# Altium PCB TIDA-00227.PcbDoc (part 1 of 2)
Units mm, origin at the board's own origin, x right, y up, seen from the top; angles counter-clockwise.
Board outline 100 x 100 mm, 2 copper layers (Top Layer, Bottom Layer), stack 1.575 mm thick; 148 components, 67 nets, 312 pads, 76 vias.
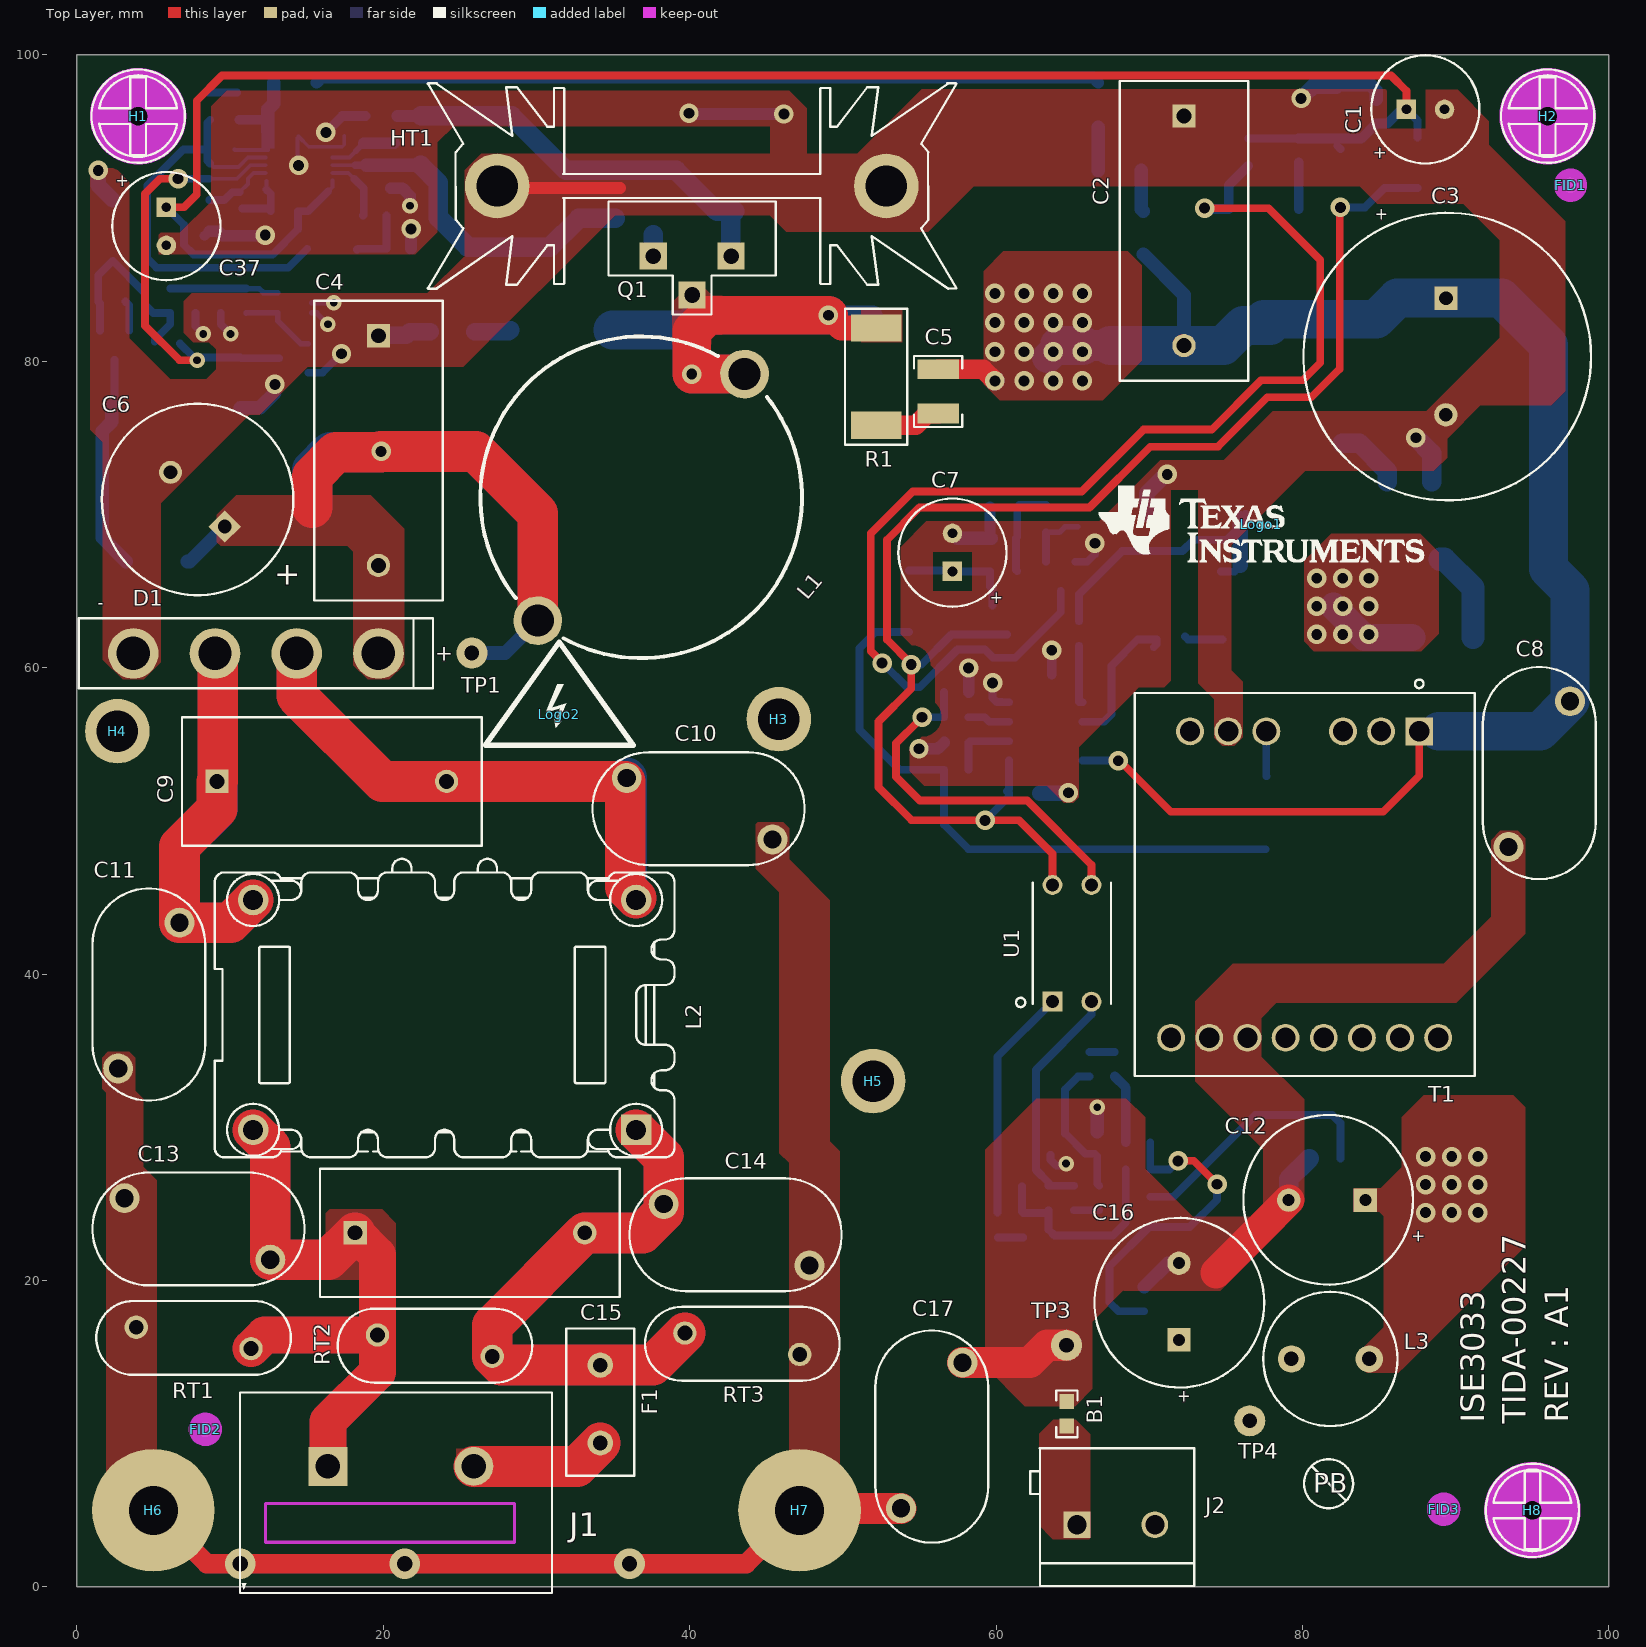
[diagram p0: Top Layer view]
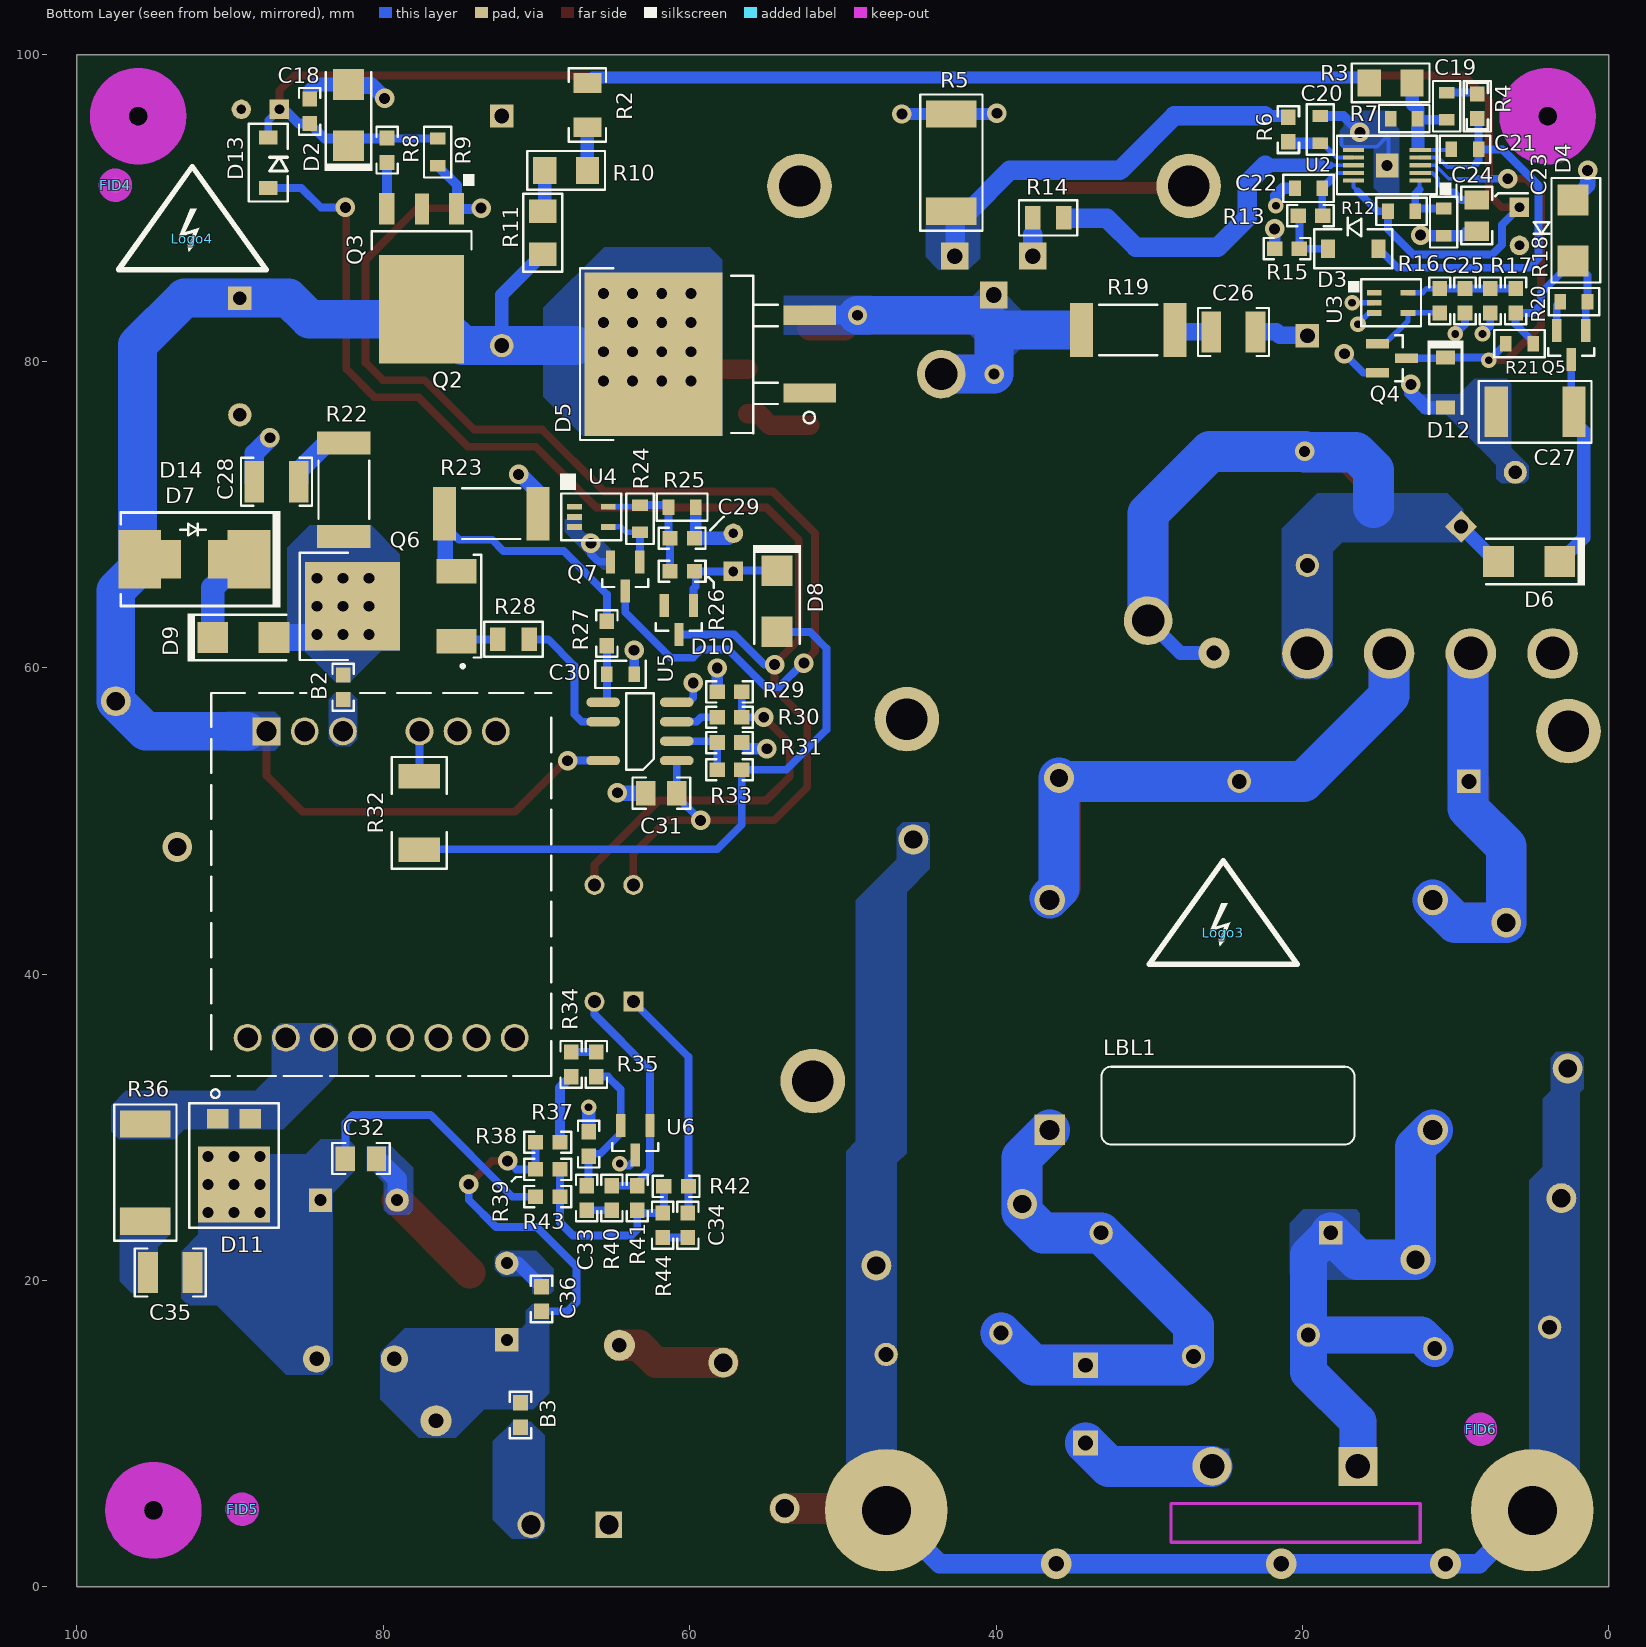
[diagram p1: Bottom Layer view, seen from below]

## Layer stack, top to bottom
Top Layer: signal copper 0.0356
Dielectric: core 1.5037, FR-4, Dk 4.8
Bottom Layer: signal copper 0.0356

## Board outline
0,0 100,0 100,100 0,100

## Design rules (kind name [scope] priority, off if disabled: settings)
AcuteAngle [All] p1: minimum=4.50000000000000E+0001 checktracksonly=FALSE
AssemblyTestPointUsage [All] p1: valid=2
Clearance Clearance_TH [IsVia vs IsThruPin] p1: gap=0.381
Clearance "Clearance_SMT to Via" [IsSMTPin vs IsVia] p2: gap=0.381
Clearance "Clearance_Via to Via" [IsVia vs IsVia] p3: gap=0.305
Clearance "Clearance_Poly to Poly" [InPolygon vs InPolygon] p4: gap=0.635
Clearance Clearance_Poly [InPolygon] p5: gap=0.635
Clearance [All] p6: gap=0.203
ComponentClearance ComponentClearance_Logo [InComponentClass('Logo')] p1: gap=1.27 collisioncheckmode=3 verticalgap=0.254 showdistances=FALSE
ComponentClearance ComponentClearance_ScrewToNut [(HasFootprint('NY PMS 440 0025 PH')) vs (HasFootprint('Keystone_1902C'))] p2: gap=0.127 collisioncheckmode=3 verticalgap=0.254 showdistances=FALSE
ComponentClearance ComponentClearance_MountingHoles [InComponentClass('Mounting Holes')] p3: gap=6.35 collisioncheckmode=3 verticalgap=2540 showdistances=FALSE
ComponentClearance ComponentClearance_SmallPassives [HasFootprint('0201*') or HasFootprint('0402*') or HasFootprint('0508') or HasFootprint('0603*') or HasFootprint('0612') or HasFootprint('0805*') or HasFootprint('0815*') or HasFootprint('0830*') or HasFootprint('1206*') or HasFootprint('1210*') or HasFootprint('1808*') or HasFootprint('1812*') or HasFootprint('1825*') or HasFootprint('2010*') or HasFootprint('2220*') or HasFootprint('2225*') or HasFootprint('2512*') or HasFootprint('2728*') or HasFootprint('3518*') vs HasFootprint('0201*') or HasFootprint('0402*') or HasFootprint('0508') or HasFootprint('0603*') or HasFootprint('0612') or HasFootprint('0805*') or HasFootprint('0815*') or HasFootprint('0830*') or HasFootprint('1206*') or HasFootprint('1210*') or HasFootprint('1808*') or HasFootprint('1812*') or HasFootprint('1825*') or HasFootprint('2010*') or HasFootprint('2220*') or HasFootprint('2225*') or HasFootprint('2512*') or HasFootprint('2728*') or HasFootprint('3518*')] p4: gap=0.508 collisioncheckmode=3 verticalgap=0.254 showdistances=FALSE
ComponentClearance ComponentClearance_THtoSMT [IsThruComponent vs IsSMTComponent] p5: gap=2.54 collisioncheckmode=3 verticalgap=0.762 showdistances=FALSE
ComponentClearance ComponentClearance_THtoTH [IsThruComponent vs IsThruComponent] p6: gap=3 collisioncheckmode=3 verticalgap=0.762 showdistances=FALSE
ComponentClearance [All] p7: gap=1.016 collisioncheckmode=3 verticalgap=0.254 showdistances=FALSE
DiffPairsRouting [All] p1: maxlimit=2.54 minlimit=0.254 mostfreqgap=0.254 maxuncoupledlength=25.4
FabricationTestPointUsage TestPointUsage [All] p1: valid=2 allowmultiple=FALSE
FabricationTestpoint Testpoint [All] p1: side=3 testpointundercomponent=TRUE minsize=1.016 maxsize=2.54 preferedsize=1.524 minholesize=0 maxholesize=1.016 preferedholesize=0.813 testpointgrid=0.025 allowsidetop=TRUE allowsidebottom=TRUE usegrid=TRUE gridtolerance=0
FanoutControl Fanout_LCC [IsLCC] p1: bgadir=Out bgaviamode=Centered fanoutstyle=Auto fanoutdirection=Alternating viagrid=0.025 // Fanout_LCC (Default Rule)
FanoutControl Fanout_BGA [IsBGA] p2: bgadir=Out bgaviamode=Centered fanoutstyle=Auto fanoutdirection=Alternating viagrid=0.025 // Fanout_BGA (Default Rule)
FanoutControl Fanout_Default [All] p4: bgadir=Out bgaviamode=Centered fanoutstyle=Auto fanoutdirection=Alternating viagrid=0.025 // Fanout_Default (Default Rule)
FanoutControl Fanout_Small [(CompPinCount < 5)] p5: bgadir=Out bgaviamode=Centered fanoutstyle=Auto fanoutdirection=OutThenIn viagrid=0.025 // Fanout_Small (Default Rule)
HoleSize [All] p1: absolutevalues=TRUE maxlimit=6.375 minlimit=0.203 maxpercent=80.000 minpercent=20.000
MinimumAnnularRing MinimumAnnularRing_ThermalPadVias [IsVia and InAnyComponent] p1: minimumring=0.15
MinimumAnnularRing [All] p2: minimumring=0.224
MinimumSolderMaskSliver MinimumSolderMaskSliver_Logo [InComponentClass('Logo') vs InComponentClass('Logo')] p1: minsoldermaskwidth=0.018
MinimumSolderMaskSliver [All] p2: minsoldermaskwidth=0.1
PlaneConnect [All] p1: planeconnectstyle=Relief reliefexpansion=0.254 reliefentries=4 reliefconductorwidth=0.254 reliefairgap=0.254
PolygonConnect [All] p1: connectstyle=Direct reliefconductorwidth=0.508 reliefentries=4 polygonreliefangle="45 Angle" airgapwidth=0.254
RoutingVias ThermalPadVias [IsVia and InAnyComponent] p1: holewidth=0.508 width=1.016 viastyle="Through Hole" minholewidth=0.406 minwidth=0.762 maxholewidth=0.508 maxwidth=1.016
RoutingVias [All] p2: holewidth=0.508 width=1.016 viastyle="Through Hole" minholewidth=0.508 minwidth=1.016 maxholewidth=1 maxwidth=2
SMDToCorner [All] p1: distance=30000
SilkToSilkClearance [All] p1: silktosilkclearance=0.127
SilkscreenOverComponentPads [All] p1: minsilkscreentomaskgap=0.127
SolderMaskExpansion [All] p1: expansion=0.064
Width [All] p1: maxlimit=5.08 minlimit=0.254 preferedwidth=0.508 checkconnectedcopper=TRUE
14 further rules are at their usual default settings.

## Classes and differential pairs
component class "Fly back converter": B1 B2 B3 C2 C7 C8 C12 C16 C17 C28 C29 C30 C31 C32 C33 C34 C35 C36 D7 D8 D9 D10 D11 D13 D14 J2 J7 J8 J9 L3 Q6 Q7 R22 R23 R24 R25 R26 R27 R28 R29 R30 R31 R32 R33 R34 R35 R36 R37 R38 R39 R40 R41 R42 R43 R44 T1 TP3 TP4 U1 U4 U5 U6
component class "Boost converter": C1 C3 C4 C5 C6 C9 C10 C11 C13 C14 C15 C18 C19 C20 C21 C22 C23 C24 C25 C26 C27 C37 D1 D2 D3 D4 D5 D6 D12 F1 HT1 J1 L1 L2 Q1 Q2 Q3 Q4 Q5 R1 R2 R3 R4 R5 R6 R7 R8 R9 R10 R11 R12 R13 R14 R15 R16 R17 R18 R19 R20 R21 RT1 RT2 RT3 TP1 U2 U3
component class hardware: !PCB1 FID1 FID2 FID3 FID4 FID5 FID6 H1 H2 H3 H4 H5 H6 H7 H8 LBL1 Logo1 ZZ1 ZZ2 ZZ3 ZZ4

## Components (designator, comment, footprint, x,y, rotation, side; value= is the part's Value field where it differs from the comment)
B1 "CIS10P700AC" 0603 64.618,11.303 r270 top (schematic designator B3)
B2 "CIS10P700AC" 0603 82.626,58.725 r270 bottom (schematic designator B1)
B3 "CIS10P700AC" 0603 71.044,11.227 r270 bottom (schematic designator B2)
C1 "CAP_ZL_6.3MM_SERIES" CAP_ZL-6.3MM 88.062,96.444 r90 top (schematic designator C13)
C2 "R46KI347050P1M" CAP_591MIL 72.263,96.012 r270 top (schematic designator C23)
C3 "33uF" CAP_EEUFC1H 89.357,80.188 r0 top (schematic designator C5)
C4 "R46KI347050P1M" CAP_591MIL 19.685,81.661 r270 top (schematic designator C6)
C5 "GRM32QR73A103KW01L" 1210 56.21,78.029 r90 top (schematic designator C2)
C6 "EEU-EE2W150" CAPPR5-12.5X20 7.884,70.983 r135 top (schematic designator C4)
C7 "CAP_ZL_6.3MM_SERIES" CAP_ZL-6.3MM 57.15,67.564 r180 top (schematic designator C30)
C8 "VY2222M35Y5US63V7" CAP_DISK_8.4MM 95.453,53.061 r270 top (schematic designator C22)
C9 "R46KI347050P1M" CAP_591MIL 9.144,52.578 r0 top (schematic designator C1)
C10 "CAP_DISK_440_[8.4MM]" CAP_DISK_8.4MM 40.64,50.8 r0 top (schematic designator C9)
C11 "CAP_DISK_440_[8.4MM]" CAP_DISK_8.4MM 4.699,38.608 r270 top (schematic designator C10)
C12 "CAP_EKZE_10MM_SERIES" CAP_ALUM-10MM 84.15,25.248 r270 top (schematic designator C24)
C13 "VY2222M35Y5US63V7" CAP_DISK_8.4MM 7.874,23.368 r180 top (schematic designator C8)
C14 "VY2222M35Y5US63V7" CAP_DISK_8.4MM 43.053,22.987 r0 top (schematic designator C7)
C15 "R46KI347050P1M" CAP_591MIL 18.161,23.114 r0 top (schematic designator C3)
C16 "CAP_EKZE_10MM_SERIES" CAP_ALUM-10MM 71.933,16.078 r180 top (schematic designator C25)
C17 "VY2222M35Y5US63V7" CAP_DISK_8.4MM 55.804,9.881 r90 top (schematic designator C37)
C18 "GRM188R71H683KA93D" 0603 84.811,96.317 r90 bottom (schematic designator C12)
C19 "C603" C603 10.592,96.647 r270 bottom
C20 "C603" C603 18.847,95.123 r270 bottom
C21 "C603" C603 9.398,93.828 r180 bottom (schematic designator C17)
C22 "C603" C603 19.609,91.288 r180 bottom (schematic designator C21)
C23 "C2012X5R1C226K125AC" 0805_HV 8.636,89.51 r270 bottom (schematic designator C16)
C24 "C603" C603 10.795,89.078 r90 bottom (schematic designator C15)
C25 "GRM188R71H683KA93D" 0603 9.398,83.947 r270 bottom (schematic designator C18)
C26 "GRM32QR73A103KW01L" 1210 24.511,81.915 r180 bottom (schematic designator C14)
C27 "C4532CH2J103K160KA" C1812 4.826,76.708 r180 bottom (schematic designator C11)
C28 "GRM32QR73A103KW01L" 1210 86.97,72.136 r0 bottom (schematic designator C29)
C29 "GRM188R71H683KA93D" 0603 60.49,68.453 r180 bottom (schematic designator C31)
C30 "C603" C603 64.516,59.563 r0 bottom (schematic designator C33)
C31 "C2012X5R1H475K125AB" 0805_HV 61.849,51.816 r180 bottom (schematic designator C32)
C32 "08053D105KAT2A" 0805_HV 81.458,27.965 r180 bottom (schematic designator C26)
C33 "06031C102JAT2A" 0603 66.726,25.387 r270 bottom (schematic designator C35)
C34 "06031C472JAT2A" 0603 60.122,23.609 r270 bottom
C35 "GRM32QR73A103KW01L" 1210 93.904,20.523 r180 bottom (schematic designator C36)
C36 "GRM188R61E106MA73" 0603 69.672,18.796 r90 bottom (schematic designator C27)
C37 "CAP_ZL_6.3MM_SERIES" CAP_ZL-6.3MM 5.842,88.773 r0 top
D1 "D-BRIDGE_GBU_SERIES" BRIDGE-INLINE-210-C 19.685,60.935 r180 top (schematic designator D2)
D2 "3SMAJ5935B-TP" SMA 82.271,96.063 r90 bottom (schematic designator D7)
D3 "D-1N4148-7-F" D_SOD123 16.688,87.351 r0 bottom (schematic designator D10)
D4 "D_ZENER_SMAZ15" DIODE_SMA 2.337,88.544 r90 bottom (schematic designator D8)
D5 "STTH8L06G" DDPAK 58.42,80.467 r0 bottom (schematic designator D1)
D6 "MURA160T3G" SMA 5.207,66.929 r0 bottom
D7 "SMCJ120A-TP" SMC 92.329,67.081 r0 bottom (schematic designator D11)
D8 "MURA160T3G" SMA 54.305,64.338 r270 bottom (schematic designator D14)
D9 "MURA160T3G" SMA 89.129,61.976 r180 bottom (schematic designator D12)
D10 "BAS21-TP" SOT-23 60.706,63.119 r270 bottom (schematic designator D15)
D11 "D-S4P_SERIES" TO-277[SMPC] 89.738,26.264 r0 bottom (schematic designator D13)
D12 "MMSZ5239B-7-F" SOD-123 10.668,78.613 r270 bottom
D13 "D-1N4148" D_SOD123 87.503,92.964 r90 bottom
D14 "P6SMB120A" SMB 92.329,67.081 r0 bottom
F1 "FUSE_RST_SERIES" FUSE_4X8.5-5.08P 34.163,9.398 r90 top
FID1 "Fiducial" Fiducial10-20 97.485,91.491 r90 top (schematic designator FID3)
FID2 "Fiducial" Fiducial10-20 8.382,10.287 r90 top
FID3 "Fiducial" Fiducial10-20 89.205,5.08 r90 top (schematic designator FID1)
FID4 "Fiducial" Fiducial10-20 97.485,91.491 r90 bottom
FID5 "Fiducial" Fiducial10-20 89.205,5.08 r90 bottom
FID6 "Fiducial" Fiducial10-20 8.382,10.287 r90 bottom
H1 "" MH3.2_H5_W6_KO8_STARHEAD 4,96 r0 top
H2 "" MH3.2_H5_W6_KO8_STARHEAD 96,96 r0 top (schematic designator H4)
H3 "" "NY PMS 440 0025 PH"#1 45.822,56.642 r0 top (schematic designator H6)
H4 "" "NY PMS 440 0025 PH"#1 2.642,55.855 r0 top (schematic designator H7)
H5 "" "NY PMS 440 0025 PH"#1 51.968,33.02 r0 top (schematic designator H8)
H6 "" "NY PMS 440 0025 PH"#2 5,5 r0 top (schematic designator H2)
H7 "" "NY PMS 440 0025 PH"#2 47.168,5 r0 top (schematic designator H3)
H8 "" MH3.2_H5_W6_KO8_STARHEAD 95,5 r0 top (schematic designator H5)
HT1 "HEATSINK_513102B02500G" HEATSINK_513201 40.132,91.44 r180 top
J1 "OSTT7022150" TERM_BLK_OSTT7022150 16.383,7.874 r0 top
J2 "ED120/2DS" CONN_ED120-2DS 67.818,4.064 r270 top
L1 "150 uH" IND_AIRD-06-151K 36.83,71.12 r320 top (schematic designator L1A)
L2 "744825510" WE-CMB_XL 24.003,37.338 r180 top
L3 "2.2uH" IND_200_MIL 81.813,14.884 r180 top
LBL1 "" Label_650x200 24.867,31.42 r180 bottom
Logo1 "" TI_Stacked_SolderMask_Small 77.313,69.369 r0 top
Logo2 "Comment" "Danger High voltage Logo" 31.496,56.973 r0 top
Logo3 "Comment" "Danger High voltage Logo" 25.168,42.687 r180 bottom
Logo4 "Comment" "Danger High voltage Logo" 92.456,88.011 r180 bottom
Q1 "TR-FQPF2N60C" TO-220V 37.617,86.868 r0 top (schematic designator Q3)
Q2 "IXTY02N50D" TO228P991X238-3N 77.495,85.395 r270 bottom (schematic designator Q1)
Q3 "TR_NFET_SOT223" TR_SOT223 77.47,87.122 r0 bottom (schematic designator Q7)
Q4 "TR-2N7002" SOT-23 14.163,80.198 r180 bottom
Q5 "TR-BSS126" SOT-23 2.464,81.051 r270 bottom (schematic designator Q2)
Q6 "AOD7N60" DPAK 78.613,64.008 r0 bottom (schematic designator Q5)
Q7 "TR-2N7002" SOT-23 64.211,65.964 r270 bottom (schematic designator Q6)
R1 "R2512" R2512 52.172,78.994 r270 top
R2 "RC1206JR-070RL" 1206 66.675,96.723 r270 bottom (schematic designator R45)
R3 "R1206" r1206 14.249,98.171 r180 bottom (schematic designator R12)
R4 "CRCW0603383KFKEA" 0603 8.585,96.647 r90 bottom (schematic designator R15)
R5 "R2512_1%" R2512 42.926,92.964 r90 bottom (schematic designator R16)
R6 "CRCW06031K27FKEA" 0603 20.93,95.123 r90 bottom (schematic designator R13)
R7 "R603" R603 13.36,95.834 r0 bottom (schematic designator R18)
R8 "RC0603FR-07220RL" 0603 79.756,93.777 r270 bottom (schematic designator R2)
R9 "R603" R603 76.454,93.65 r90 bottom (schematic designator R3)
R10 "R1206" R1206 68.072,92.456 r180 bottom (schematic designator R8)
R11 "R1206" R1206 69.596,88.392 r90 bottom (schematic designator R5)
R12 "R603" R603 13.538,89.789 r180 bottom (schematic designator R4)
R13 "CRCW060340K2FKEA" 0603 19.482,89.51 r180 bottom (schematic designator R19)
R14 "R0805_1%" R0805 36.601,89.357 r0 bottom (schematic designator R10)
R15 "RC0603FR-074K02L" 0603 21.006,87.351 r180 bottom (schematic designator R20)
R16 "CRCW06031M00FKEA" 0603 11.049,83.947 r270 bottom (schematic designator R14)
R17 "CRCW0603127KFKEA" 0603 7.747,83.947 r270 bottom
R18 "CRCW0603402KFKEA" 0603 6.096,83.947 r90 bottom (schematic designator R11)
R19 "RHC2512FT68R0" 2512M 31.369,82.042 r0 bottom (schematic designator R7)
R20 "R603" R603 2.286,83.896 r180 bottom (schematic designator R6)
R21 "R603" R603 5.842,81.153 r0 bottom (schematic designator R9)
R22 "CRCW2512162RFKEGHP" 2512M 82.575,71.603 r270 bottom
R23 "ERJ-1TRQF1R2U" 2512M 72.949,70.053 r180 bottom (schematic designator R36)
R24 "R603" r603 63.246,69.723 r270 bottom (schematic designator R25)
R25 "R603" r603 60.49,70.485 r180 bottom (schematic designator R29)
R26 "CRCW060378K7FKEA" 0603 60.49,66.294 r180 bottom
R27 "CRCW06031K00FKEA" 0603 65.405,62.23 r90 bottom (schematic designator R32)
R28 "R0805_1%" r0805 71.501,61.849 r0 bottom (schematic designator R23)
R29 "CRCW060330K1FKEA" 0603 57.404,58.42 r180 bottom (schematic designator R43)
R30 "CRCW06030000Z0EA" 0603 57.404,56.769 r0 bottom (schematic designator R39)
R31 "CRCW060324K3FKEA" 0603 57.404,55.118 r0 bottom (schematic designator R30)
R32 "CRCW20108R20JNEF" 2010M 77.648,50.521 r90 bottom (schematic designator R21)
R33 "CRCW0603110KJNEA" 0603 57.404,53.34 r180 bottom (schematic designator R27)
R34 "CRCW06030000Z0EA" 0603 67.742,34.112 r270 bottom (schematic designator R38)
R35 "CRCW0603226KFKEA" 0603 66.091,34.112 r90 bottom (schematic designator R40)
R36 "R2512" R2512 95.529,27.051 r270 bottom (schematic designator R44)
R37 "CRCW060344K2FKEA" 0603 66.599,28.905 r270 bottom (schematic designator R42)
R38 "CRCW06030000Z0EA" 0603 69.266,29.032 r0 bottom (schematic designator R31)
R39 "CRCW06030000Z0EA" 0603 69.266,27.254 r0 bottom (schematic designator R28)
R40 "CRCW06030000Z0EA" 0603 65.075,25.387 r270 bottom (schematic designator R41)
R41 "CRCW06031K00FKEA" 0603 63.424,25.387 r270 bottom (schematic designator R37)
R42 "CRCW060310K0JNEA" 0603 60.884,26.149 r0 bottom (schematic designator R34)
R43 "CRCW06030000Z0EA" 0603 69.266,25.476 r0 bottom (schematic designator R24)
R44 "CRCW06034K99FKEA" 0603 61.773,23.609 r270 bottom (schematic designator R33)
RT1 "MOV_B72210SXXXXK101" DISK-472 7.62,16.256 r0 top (schematic designator RT2)
RT2 "MOV_B72210SXXXXK101" DISK-472 23.368,15.748 r0 top (schematic designator RT1)
RT3 "MOV_B72210SXXXXK101" DISK-472 43.434,15.875 r180 top
T1 "750342415" WE_750342415 80.137,45.847 r270 top
TP1 "TESTPOINT" TESTPOINT 25.781,60.96 r0 top
TP3 "TESTPOINT" TESTPOINT 64.592,15.773 r0 top (schematic designator TP4)
TP4 "TESTPOINT" TESTPOINT 76.556,10.846 r0 top (schematic designator TP3)
U1 "LTV-817" DIP762W60P254L460H350Q4B 64.948,42.012 r90 top (schematic designator U5)
U2 "TPS40210DGQ" DGQ_10PWP 14.478,92.786 r0 bottom (schematic designator U1)
U3 "LMS33460" SC-70-5 14.224,83.82 r270 bottom (schematic designator U2)
U4 "LMS33460" SC-70-5 66.421,69.85 r270 bottom
U5 "UCC28740D" D0007A_N 63.246,55.84 r0 bottom (schematic designator U3)
U6 "TL431AIDBZ" SOT-23 63.551,29.159 r270 bottom
ZZ1 "" AssemblyNoteLabel 4.699,122.047 r0 top
ZZ2 "" AssemblyNote 4.572,119.507 r0 top
ZZ3 "" AssemblyNote 4.953,117.475 r0 top
ZZ4 "" AssemblyNote 5.08,114.808 r0 top

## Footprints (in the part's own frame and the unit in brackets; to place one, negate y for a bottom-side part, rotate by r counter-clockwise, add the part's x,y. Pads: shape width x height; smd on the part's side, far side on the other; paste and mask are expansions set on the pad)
0603 [mm] "0603 from SM-752 data"
  rect 1x0.95 smd: 1(-0.8,0) 2(0.8,0)
  silkscreen extent -1.52,-0.69 1.52,0.69, body extent -0.87,-0.47 0.87,0.47, height 0.85
0805_HV [mil] "0805 with 30mil clearance between pads"
  rect 50x63 smd: 1(-40,0) 2(40,0)
  silkscreen extent -74,-40 74,40, body extent -43,-29 43,29, height 43
1206 [mm] "1206 from SM-752 data"
  rect 1.3x1.85 smd: 1(-1.45,0) 2(1.45,0)
  silkscreen extent -2.4,-1.21 2.4,1.21, body extent -1.7,-0.9 1.7,0.9, height 1.35
1210 [mm] "1210 from SM-752 data"
  rect 1.3x2.7 smd: 1(-1.45,0) 2(1.45,0)
  silkscreen extent -2.32,-1.57 2.32,1.57, body extent -1.7,-1.35 1.7,1.35, height 1.35
2010M [mm]
  rect 1.6x2.7 smd: 1(-2.4,0) 2(2.4,0)
  silkscreen extent -3.65,-1.8 3.65,1.8, body extent -2.73,-1.45 2.73,1.45, height 1.66
2512M [mm] "Chip Resistor, Body 6.3x3.2mm, IPC Low Density"
  rect 1.5x3.5 smd: 1(-3.05,0) 2(3.05,0)
  silkscreen extent -1.9,-1.65 1.9,1.65, body extent -3.22,-1.67 3.22,1.67, height 0.71
AssemblyNote [mm] "Assembly Note"
AssemblyNoteLabel [mm] "Assembly Note for PCB Labels"
BRIDGE-INLINE-210-C [mil]
  round 130 hole 86: 1(0,0) 2(210,0) 3(420,0) 4(630,0)
  silkscreen extent -140,-90 770,90
C603 [mil]
  rect 30x40 smd: 1(-35,0) 2(35,0)
C1812 [mil]
  rect 60x130 smd: 1(-100,0) 2(100,0)
CAP_591MIL [mil]
  rect 60x60 hole 38: 1(0,0)
  round 60 hole 38: 2(590,0)
  silkscreen extent -90,-165 680,165
CAP_ALUM-10MM [mil]
  rect 60x60 hole 31: 1(0,-2)
  round 60 hole 31: 2(0,-199)
  silkscreen extent -219,-315 217,120
CAP_DISK_8.4MM [mil]
  round 77 hole 47: 1(-187,79) 2(187.5,-79)
  silkscreen extent -275,-145 270,145
CAP_EEUFC1H [mil]
  rect 60x60 hole 35: 1(0.1,155)
  round 60 hole 35: 2(0,-145)
  silkscreen extent -366,-365 373,374
CAP_ZL-6.3MM [mil]
  rect 50x50 hole 25: 1(0,50.5)
  round 50 hole 25: 2(0,-47.5)
  silkscreen extent -139,-137 139,141
CAPPR5-12.5X20 [mm] "Capacitor, Electrolytic, Radial; Body 12.5 x 20 mm (Dia.xH typ); Pin Spacing 5 mm (typ)"
  rect 1.5x1.5 hole 0.9: 1(-2.5,0)
  round 1.5 hole 0.9: 2(2.5,0)
  silkscreen extent -6.25,-6.25 6.25,6.25, body extent -6.01,-6.01 6.01,6.01, height 22
CONN_ED120-2DS [mm] "ONSHORE"
  rect 1.75x1.75 hole 1.25: 1(0,-2.54)
  round 1.75 hole 1.25: 2(0,2.54)
  silkscreen extent -5,-5.6 4,5.12, body extent -5,-5.6 4.15,5.12, height 13.1
D0007A_N [mm] "SOIC, 7-Leads, Body 4.9x3.9mm, Pitch 1.27mm, IPC Medium Density"
  oval 2.2x0.6 smd: 1(-2.4,1.905) 2(-2.4,0.635) 3(-2.4,-0.635) 4(-2.4,-1.905) 5(2.4,-1.905) 6(2.4,-0.635) 8(2.4,1.905)
  silkscreen extent -0.9,-2.5 0.9,2.5, body extent -3,-2.5 3,2.5, height 1.54
D_SOD123 [mil]
  rect 36x48 smd: 1(65,0) 2(-65,0)
  silkscreen extent -21,-79 14,-32
"Danger High voltage Logo" [mm]
  silkscreen extent -4.83,-2.03 4.83,4.7
DDPAK [mil] "D2-PAK, 3-Pads, Body 9.7x10.4mm (max), TO-263AB, using Vishay Silionix recommended pad sizes"
  rect 135x49.49 smd: 1(-246.06,100) 3(-246.06,-100)
  rect 355x420 smd paste-181.1: 4(155.51,0)
  silkscreen extent -260,-220 344,220, body extent -295,-202 324,202, height 180
DGQ_10PWP [mil]
  rect 55x11 smd: 1(-84.5,39) 2(-84.5,19.3) 3(-84.5,-0.4) 4(-84.5,-20.1) 5(-84.5,-39.8) 6(86.5,-39.8) 7(86.5,-20.1) 8(86.5,-0.4) 9(86.5,19.3) 10(86.5,39)
  rect 57.87x61.81 smd: 11(0,0)
  silkscreen extent -165,-76 129,75
DIODE_SMA [mil]
  rect 80x80 smd: 1(-78.5,0) 2(78.5,0)
  silkscreen extent -9,61 21,101
DIP762W60P254L460H350Q4B [mm] "LITE-ON"
  rect 1.3x1.3 hole 0.85: 1(-3.81,1.27)
  round 1.3 hole 0.85: 2(-3.81,-1.27) 3(3.81,-1.27) 4(3.81,1.27)
  silkscreen extent -3.96,-2.55 3.96,2.55, body extent -3.96,-2.55 3.96,2.55, height 4.5
DISK-472 [mil]
  round 60 hole 38: 1(-147.5,27.5) 2(147.5,-27.5)
  silkscreen extent -250,-95 250,95
DPAK [mm] "D-PAK, 3-Pads, Body 6.22x6.73mm (max), TO-252AA using nominal STEP model"
  rect 2.6x1.6 smd: 1(-3.4,2.28) 3(-3.4,-2.28)
  rect 6.2x5.8 smd paste-2.9: 4(3.4,0)
  silkscreen extent -5,-3.5 6.83,3.99, body extent -3.86,-3.29 5.84,3.29, height 2.48
Fiducial10-20 [mm]
  round 1 smd paste-0.5 mask+0.5: 1(0,0)
  Top Layer keep-out circle w1.178: c0,0 r0.5
FUSE_4X8.5-5.08P [mil]
  round 65 / inner rect 65x65 / far side rect 65x65 hole 38: 1(0,0) 2(200,0)
  silkscreen extent -84,-87 294,88
HEATSINK_513201 [mil]
  round 166 hole 106.5: 1(-500,0) 2(500,0)
  silkscreen extent -680,-264 678,264
IND_200_MIL [mil]
  round 70 hole 37: 1(-100,0) 2(100,0)
  silkscreen extent -172,-172 172,172
IND_AIRD-06-151K [mm]
  round 3.175 hole 2.108: 1(0,-10.5) 2(0,10.5)
  silkscreen extent -10.5,-10.3 10.5,10.29, body extent -10.42,-10.48 10.5,10.48, height 21.5
Label_650x200 [mil] "Thermal Transfer Label"
  round 1 on Mech14: 0(0,0)
  silkscreen extent -325,-100 325,100, body extent -326,-101 326,101, height 1
MH3.2_H5_W6_KO8_STARHEAD [mil]
  round 20 / inner round 142 / far side round 20 hole 128 unplated mask+64: 1(0,0)
  Keep-Out Layer circle w100: c0,0 r74
  silkscreen extent -120,-120 120,120
"NY PMS 440 0025 PH"#1 [mm] "4-40 nylon screw and mounting hole"
  round 4.216 hole 2.705: 1(0,0)
  body extent -3.3,-3.3 3.3,3.3, height 2.69
"NY PMS 440 0025 PH"#2 [mm] "4-40 nylon screw and mounting hole"
  round 8 hole 3.2: 1(0,0)
  body extent -3.3,-3.3 3.3,3.3, height 2.69
R603 [mil]
  rect 30x40 smd: 1(-35,0) 2(35,0)
r603 [mil]
  rect 30x40 smd: 1(-35,0) 2(35,0)
R0805 [mil]
  rect 40x60 smd: 1(-40,0) 2(40,0)
r0805 [mil]
  rect 40x60 smd: 1(-40,0) 2(40,0)
r1206 [mil]
  rect 60x70 smd: 1(-55,0) 2(55,0)
R1206 [mil]
  rect 60x70 smd: 1(-55,0) 2(55,0)
R2512 [mil]
  rect 70x130 smd: 1(-125,0) 2(125,0)
SC-70-5 [mil]
  rect 15x38 smd: 1(-25.9,-43.4) 2(0.1,-43.4) 3(26.1,-43.4) 4(26.1,43.6) 5(-25.9,43.6)
  silkscreen extent -60,-110 60,77
SMA [mm] "Molded Diode, 2-Leads, Body 4.3x2.6mm, IPC Medium Density, based on OnSemi component dimensions and land pattern"
  rect 2x2 smd: 1(-2,0) 2(2,0)
  silkscreen extent -3.66,-1.57 2.79,1.57, body extent -2.6,-1.3 2.6,1.3, height 2.42
SMB [mil]
  rect 90x100 smd: 1(-80,0) 2(80,0)
  silkscreen extent -29,-91 36,-61
SMC [mil] "Molded Diode, 2-Leads, Body 6.9x5.8mm, IPC Medium Density, based on OnSemi component dimensions and land patterns"
  rect 110x150 smd: 1(-140.49,0) 2(140.49,0)
  silkscreen extent -221,-124 189,124, body extent -156,-116 156,116, height 91
SOD-123 [mm] "On Semi recommended land pattern"
  rect 0.915x1.22 smd: 1(-1.637,0) 2(1.637,0)
  silkscreen extent -2.74,-1.17 2.03,1.17, body extent -1.93,-0.9 1.93,0.9, height 1.35
SOT-23 [mm] "SOT23, 3-Leads, Body 2.9x1.3mm, Pitch 0.95mm, Lead Span 2.5mm, IPC Medium Density"
  rect 1.5x0.6 smd: 1(-0.95,0.95) 2(-0.95,-0.95) 3(0.95,0)
  silkscreen extent 0.2,-1.5 0.7,1.5, body extent -1.16,-1.45 1.21,1.45, height 1
TERM_BLK_OSTT7022150 [mm]
  rect 2.54x2.54 hole 1.6: 1(0,0)
  round 2.54 hole 1.6: 2(9.525,0)
  silkscreen extent -5.74,-8.28 14.63,4.83, body extent -5.3,-8 14.33,4.5, height 21.6
TESTPOINT [mil]
  round 80 hole 37.99: 1(0,0)
TI_Stacked_SolderMask_Small [mm]
  silkscreen extent -10.63,-2.49 10.63,2.49
TO228P991X238-3N [mm] "IC, MOSFET N-CH, 500V, 200MA, DPAK"
  rect 2.05x1 smd: 1(-4.55,2.28) 3(-4.55,-2.28)
  rect 7.1x5.55 smd: 2(2,0)
  silkscreen extent -6.71,-3.25 -1.9,3.37, body extent -2.03,-3.27 4.07,3.27, height 2.38
TO-220V [mil]
  rect 70x70 hole 40: 1(0,0) 2(100,-100) 3(200,0)
  silkscreen extent -115,-150 315,140
TO-277[SMPC] [mil]
  rect 55x50 smd: 1(42,-168.6) 2(-42,-168.6)
  rect 185x195 smd: 3(0,0)
  silkscreen extent -115,-209 115,111
TR_SOT223 [mil]
  rect 35x80 smd: 1(-90.6,-110.9) 2(0,-110.9) 3(90.6,-110.9)
  rect 130x80 smd: 4(0,109.5)
  silkscreen extent -135,-200 -105,-170
WE-CMB_XL [mm] "Wurth"
  rect 2x2 hole 1.3: 1(-12.5,7.5)
  round 2 hole 1.3: 6(12.5,7.5) 7(12.5,-7.5) 12(-12.5,-7.5)
  silkscreen extent -15,-10.18 15,9.3, body extent -15.25,-10.5 15.25,10.5, height 35
WE_750342415 [mm] "TRANSFOERMER, TH, 14-PIN"
  rect 1.82x1.82 / inner round 1.82 / far side rect 1.82x1.82 hole 1.32: 1(-10,7.48)
  round 1.82 hole 1.32: 2(-10,4.99) 3(-10,2.5) 4(-10,-2.5) 5(-10,-4.99) 6(-10,-7.48) 7(10,-8.715) 8(10,-6.225) 9(10,-3.735) 10(10,-1.245) 11(10,1.245) 12(10,3.735) 13(10,6.225) 14(10,8.715)
  silkscreen extent -13.38,-11.1 12.5,11.1, body extent -12.5,-11.1 12.5,11.1, height 16

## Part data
B1 B2 B3: library part BEAD-BLM18AG_SERIES, "FERRITE CHIP 70 OHM 4000MA 0603"
C1 C7 C37: "CAP ALUM 33UF 35V 20% RADIAL"
C2 C4 C9 C15: library part CAP_ECQU2A104XL, "CAP FILM 0.47UF 560VDC RADIAL"
C3: library part CAP_KXG-18X25MM_HORIZ_SERIES, "CAP ALUM 33UF 450V 20% RADIAL"
C5 C26 C28 C35: "CAP, CERM, 0.01uF, 1000V, +/-10%, X7R, 1210"
C6: library part EEUED2W100, "CAP ALUM 15UF 450V 20% RADIAL"
C8 C13 C14 C17: library part CAP_DISK_440_[8.4MM], "CAP CER 2200PF 300VAC 20% RADIAL"
C10 C11: "CAP CER 330PF 300VAC 10% RADIAL"
C12 C16: "CAP ALUM 470UF 35V 20% RADIAL"
C18 C25 C29: "CAP, CERM, 0.068uF, 50V, +/-10%, X7R, 0603"
C19: "CAP CER 0.1UF 50V 10% X7R 0603"
C20 C30: "CAP, CERM, 2200pF, 50V, +/-10%, X7R, 0603"
C21 C24: "CAP CER 470PF 50V 5% NP0 0603"
C22: "CAP CER 1UF 25V 10% X7R 0603"
C23: "CAP, CERM, 22uF, 16V, +/-10%, X5R, 0805"
C27: library part C1812, "Corporation CAP CER 10000PF 630V 10% CH 1812"
C31: "CAP, CERM, 4.7uF, 50V, +/-10%, X5R, 0805"
C32: "CAP, CERM, 1uF, 25V, +/-10%, X5R, 0805"
C33: "CAP, CERM, 1000pF, 100V, +/-5%, X7R, 0603"
C34: "CAP, CERM, 4700pF, 100V, +/-5%, X7R, 0603"
C36: "CAP, CERM, 10uF, 25V, +/-20%, X5R, 0603"
D1: "RECT BRIDGE GPP 8A 600V GBU"
D2: "Diode, Zener, 27V, 3W, SMA"
D3 D13: "Diode, Signal, 300-mA, 75-V, 350-mW"
D4: "Diode, Zener,15-V, 1W"
D5: "Diode, Ultrafast, 600V, 8A, DDPAK"
D6 D8 D9: "Diode, Ultrafast, 600V, 1A, SMA"
D7: "Diode, TVS, Uni, 120V, 1500W, SMC"
D10: "Diode, P-N, 200V, 200A, SOT-23"
D11: "Diode Schottky, 8A, 100V"
D12: "Diode, Zener, 9.1V, 500mW, SOD-123"
D14: library part D-P6SMBXXXA, "TVS DIODE 102VWM 165VC SMD"
F1: "FUSE SLOW 250VAC 5A RADIAL"
FID1 FID2 FID3 FID4 FID5 FID6: "Fiducial mark.  There is nothing to buy or mount."
H1 H2 H3 H4 H5 H6 H7 H8: library part "NY PMS 440 0025 PH", "Mounting Hole M3 3.5mm"
HT1: library part HEATSINK_513201, "HEATSINK TO-220 W/PINS 1.5\"TALL"
J1: "Terminal Block, 30A, 9.52mm (.375) Pitch, 2-Pos, TH"
J2: "TERMINAL BLOCK 5.08MM VERT 2POS, TH"
L1: library part IND_AIRD-06-151K, "INDUCTOR 150UH 4.0A 10%"
L2: "Coupled inductor, 10mH, 5A, 0.055 ohm, TH"
L3: library part IND_RFB0807_SERIES, "INDUCTOR 2.2UH 4.1A RADIAL"
LBL1: library part THT-14-423-10, "Thermal Transfer Printable Labels, 0.650\" W x 0.200\" H - 10,000 per roll"
Logo1: library part TI_Logo, "Texas Instrument Corporate Signature"
Q1: "MOSFET, Nch, 600-V, 20A, 0.199 Ohms"
Q2: "DISCRETE, MOSFET N-CH 500V 200MA, DPAK"
Q3: "MOSFET N-CH 600V 120MA SOT-223"
Q4 Q7: "MOSFET N-CH 60V 260MA SOT-23"
Q5: "MOSFET N-CH 600V 21MA SOT23"
Q6: "MOSFET, N-CH, 600V, 7A, DPAK"
R1 R36: "RES 330 OHM 1W 5% 2512"
R2: "RES, 0 ohm, 5%, 0.25W, 1206"
R3 R10 R11: "RES 649K OHM 1/4W 1% 1206 SMD"
R4: "RES, 383k ohm, 1%, 0.1W, 0603"
R5: "RES 0.02 OHM 1W 1% 2512 SMD"
R6: "RES, 1.27k ohm, 1%, 0.1W, 0603"
R7: "RES 3.83K OHM 1/10W 1% 0603 SMD"
R8: "RES, 220 ohm, 1%, 0.1W, 0603"
R9: "RES 44.2K OHM 1/10W 1% 0603 SMD"
R12: "RES 1.33M OHM 1/10W 1% 0603 SMD"
R13: "RES, 40.2k ohm, 1%, 0.1W, 0603"
R14: "RES 15.0 OHM 1/8W 1% 0805 SMD"
R15: "RES, 4.02k ohm, 1%, 0.1W, 0603"
R16: "RES, 1.00Meg ohm, 1%, 0.1W, 0603"
R17: "RES, 127k ohm, 1%, 0.1W, 0603"
R18: "RES, 402k ohm, 1%, 0.1W, 0603"
R19: library part CRCW251222R0JNEGHP, "RES 68 OHM 2W 1% 2512"
R20 R25: "RES 30.1K OHM 1/10W 1% 0603 SMD"
R21: "RES 1.00M OHM 1/10W 1% 0603 SMD"
R22: library part CRCW2512332RFKEG, "RES 162 OHM 1.5W 1% 2512 SMD"
R23: "RES, 1.20 ohm, 1%, 1W, 2512"
R24: "RES 301K OHM 1/10W 1% 0603 SMD"
R26: "RES, 78.7k ohm, 1%, 0.1W, 0603"
R27 R41: "RES, 1.00k ohm, 1%, 0.1W, 0603"
R28: "RES 10.0 OHM 1/8W 1% 0805 SMD"
R29: "RES, 30.1k ohm, 1%, 0.1W, 0603"
R30 R34 R38 R39 R40 R43: "RES, 0 ohm, 5%, 0.1W, 0603"
R31: "RES, 24.3k ohm, 1%, 0.1W, 0603"
R32: "RES, 8.2 ohm, 5%, 0.75W, 2010"
R33: "RES, 110k ohm, 5%, 0.1W, 0603"
R35: "RES, 226k ohm, 1%, 0.1W, 0603"
R37: "RES, 44.2k ohm, 1%, 0.1W, 0603"
R42: "RES, 10k ohm, 5%, 0.1W, 0603"
R44: "RES, 4.99k ohm, 1%, 0.1W, 0603"
RT1 RT2 RT3: "MOV, 300V"
T1: "TRANSFOERMER, 856uH, +/-10%, TH, 14-PIN"
TP1 TP3 TP4: "TEST POINT.  No entry in BOM."
U1: "Opto-Isolator, 1 Channel, TH"
U2: "IC REG CTRLR BST FLYBK CM 10MSOP"
U3 U4: "IC DETECTOR UNDER VOLT 3V SC70-5"
U5: "Constant-Voltage, Constant-Current Flyback Controller Using Opto-Coupler Feedback, D0007A"
U6: "IC VREF SHUNT PREC ADJ SOT23-3"
ZZ1: library part AssemblyNoteLabel, "This Assembly Note is for PCB labels only"
ZZ2: library part AssemblyNote, "These assemblies are ESD sensitive, ESD precautions shall be observed."
ZZ3: library part AssemblyNote, "These assemblies must be clean and free from flux and all contaminants. Use of no clean flux is not acceptable."
ZZ4: library part AssemblyNote, "These assemblies must comply with workmanship standards IPC-A-610 Class 2, unless otherwise specified."

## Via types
v1: diameter 1.27, hole 0.711, Top Layer to Bottom Layer, tented both sides, 65 vias
v2: diameter 1.016, hole 0.508, Top Layer to Bottom Layer, tented both sides, 8 vias
v3: diameter 2, hole 1, Top Layer to Bottom Layer, tented both sides, 3 vias

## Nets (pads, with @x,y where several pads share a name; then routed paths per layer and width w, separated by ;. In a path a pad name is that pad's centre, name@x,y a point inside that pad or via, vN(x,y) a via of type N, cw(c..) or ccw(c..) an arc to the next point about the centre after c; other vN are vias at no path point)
15V: B3.2 J2.2
EARTH: C10.2 C11.2 C13.2 C14.2 C17.1 H6.1 H7.1 RT1.1 RT3.1 | length 96.8
  Top Layer w1.27: H6.1@5,5 8.476,1.524 43.692,1.524 H7.1@47.168,5
  Top Layer w2.032: H7.1@47.168,5 47.299,5.131 C17.1@53.797,5.131
  Bottom Layer w1.27: H6.1@5,5 8.476,1.524 43.692,1.524 H7.1@47.168,5
  other v3: 10.668,1.524 21.4,1.524 36.068,1.524
NetB2_1: B2.1 D9.2 Q6.4 R22.2 | length 6
  Bottom Layer w1.778: Q6.4@82.013,64.008 84.045,61.976 D9.2@87.129,61.976
  other v1: 80.924,62.179 82.626,62.179 84.328,62.179 80.924,64.008 82.626,64.008 84.328,64.008 80.924,65.837 82.626,65.837 84.328,65.837
NetB2_2: B2.2 T1.3
NetB3_1: B3.1 C16.1 C36.1 L3.2 R38.2 R39.2 TP4.1 | length 21.7
  Top Layer w0.508: v1(71.882,27.813) 72.898,27.813 v1(74.422,26.289)
  Bottom Layer w0.508: C36.1@69.672,17.996 67.983,17.996 67.393,18.586 67.393,20.911 69.977,23.495 72.644,23.495 74.422,25.273 v1(74.422,26.289) ; R38.2@70.066,29.032 R39.2@70.066,27.254 71.323,27.254 v1(71.882,27.813)
NetC1_1: C1.1 C18.1 C37.1 D2.1 D13.1 R8.1 R9.2 R12.1 U2.10 | length 119.1
  Top Layer w0.508: C37.1@5.842,90.056 6.998,90.056 7.823,90.881 7.823,97.003 9.474,98.654 85.776,98.654 86.779,97.65 C1.1@86.779,96.444
  Bottom Layer w0.254: 16.402,91.103 16.675,91.376 U2.10@16.675,91.796
  Bottom Layer w0.508: C37.1@5.842,90.056 6.985,88.913 6.985,87.605 7.62,86.97 12.776,86.97 14.427,88.621 R12.1@14.427,89.789 15.088,89.789 16.402,91.103 ; R9.2@76.454,94.539 79.718,94.539 R8.1@79.756,94.577 ; D2.1@82.271,94.063 D2.1@82.474,93.86 ; C1.1@86.462,96.444 C1.1@86.779,96.444 87.503,95.72 D13.1@87.503,94.615
  Bottom Layer w0.635: R8.1@79.718,94.539 83.833,94.539 C18.1@84.811,95.517 85.535,95.517 C1.1@86.462,96.444
NetC2_2: C2.2 C3.1 C5.2 C8.1 D5.4 D7.2 D14.2 Q2.2 Q3.4 R11.1 T1.1 U5.8 | length 107.9
  Top Layer w0.508: v1(67.97,53.924) 68.072,53.924 71.399,50.597 85.268,50.597 87.617,52.946 T1.1@87.617,55.847
  Top Layer w1.27: C5.2@56.21,79.479 59.154,79.479 v1(59.919,78.715) ; C2.2@72.187,81.102 C2.2@72.263,81.026
  Bottom Layer w0.508: U5.8@65.646,53.935 65.661,53.95 68.047,53.95 68.072,53.924 v1(67.97,53.924)
  Bottom Layer w0.889: R11.1@69.596,86.995 72.263,84.328 C2.2@72.263,81.026
  Bottom Layer w2.032: D5.4@63.361,80.239 D5.4@64.148,81.026 ; D5.4@63.894,81.026 D5.4@64.135,81.026 ; D5.4@65.634,81.026 67.462,81.026
  Bottom Layer w2.54: D5.4@64.135,81.026 64.148,81.026 D5.4@65.634,81.026 ; 67.462,81.026 C2.2@72.263,81.026 74.828,81.026 76.141,82.338 Q2.2@77.876,82.338 ; Q2.2@77.47,82.745 84.802,82.745 86.182,84.125 C3.1@89.36,84.125 92.989,84.125 96.05,81.064 96.05,66.459 97.46,65.049 C8.1@97.46,57.81 95.504,55.855 88.9,55.855
  other v1: 61.824,78.715 63.729,78.715 65.634,78.715 59.919,80.62 61.824,80.62 63.729,80.62 65.634,80.62 59.919,82.525 61.824,82.525 63.729,82.525 65.634,82.525 59.919,84.43 61.824,84.43 63.729,84.43 65.634,84.43
NetC4_2: C4.2 C6.1 D1.1 D6.2 L1.1 TP1.1 | length 61.7
  Top Layer w2.667: 15.367,70.46 15.367,72.517 16.916,74.066 v1@19.863,74.066 ; v1(19.863,74.117) 26.035,74.117 30.081,70.071 L1.1@30.081,63.077
  Bottom Layer w0.889: D6.2@7.207,66.929 7.366,66.929 C6.1@9.652,69.215 ; D1.1@19.685,61.443 D1.1@20.193,60.935 ; TP1.1@25.781,60.96 27.964,60.96 L1.1@30.081,63.077
  Bottom Layer w2.667: 15.367,70.46 15.367,72.898 16.535,74.066 v1@19.863,74.066 ; v1(19.863,74.117) 26.035,74.117 30.081,70.071 L1.1@30.081,63.077
NetC5_1: C5.1 R1.2 | length 4.4
  Top Layer w1.27: R1.2@52.172,75.819 54.749,75.819 55.509,76.579 C5.1@56.21,76.579
NetC7_1: C7.1 D8.1 D10.1 R26.2 | length 7.6
  Bottom Layer w0.508: D8.1@54.305,66.338 57.093,66.338 C7.1@57.15,66.281 59.588,66.281 59.601,66.294 59.601,65.306 59.756,65.151 D10.1@59.756,64.069
NetC9_1: C9.1 C11.1 D1.3 L2.7 | length 48.1
  Top Layer w2.667: D1.3@9.017,60.935 9.195,60.757 C9.1@9.195,52.578 ; C9.1@9.144,52.578 9.144,50.775 6.706,48.336 C11.1@6.706,43.358 10.023,43.358 L2.7@11.503,44.838
  Bottom Layer w2.667: D1.3@9.195,60.935 9.195,50.825 6.706,48.336 C11.1@6.706,43.358 10.023,43.358 L2.7@11.503,44.838
NetC9_2: C9.2 C10.1 D1.2 L2.12 | length 69
  Top Layer w2.667: D1.2@14.351,60.935 14.351,58.166 19.939,52.578 C9.2@24.13,52.578 35.789,52.578 35.789,45.68 L2.12@36.503,44.965
  Bottom Layer w2.667: D1.2@14.351,60.935 14.351,58.166 19.939,52.578 C9.2@24.13,52.578 C10.1@35.789,52.578 ; C10.1@35.89,52.807 35.89,45.578 L2.12@36.503,44.965
NetC12_1: C12.1 C32.1 C35.2 D11.3 L3.1 R43.2 | length 17.1
  Bottom Layer w0.508: R43.2@70.066,25.476 71.577,25.476 76.911,30.81 81.94,30.81 82.474,30.277 C32.1@82.474,27.965
  other v1: 88.036,24.435 89.738,24.435 91.44,24.435 88.036,26.264 89.738,26.264 91.44,26.264 88.036,28.092 89.738,28.092 91.44,28.092
NetC13_1: C13.1 C15.1 J1.1 L2.6 RT1.2 RT2.1 | length 82
  Top Layer w2.413: RT1.2@11.367,15.557 12.255,16.447 RT2.1@19.621,16.447 ; J1.1@16.383,7.874 16.383,10.795 19.621,14.034 RT2.1@19.621,16.447 ; C15.1@18.161,23.114 19.621,21.653 RT2.1@19.621,16.447
  Top Layer w2.667: L2.6@11.503,29.838 12.624,28.717 C13.1@12.624,21.361 16.408,21.361 C15.1@18.161,23.114
  Bottom Layer w2.413: RT1.2@11.367,15.557 12.255,16.447 RT2.1@19.621,16.447 ; J1.1@16.383,7.874 16.383,10.795 19.621,14.034 RT2.1@19.621,16.447 ; C15.1@18.161,23.114 19.621,21.653 RT2.1@19.621,16.447
  Bottom Layer w2.667: L2.6@11.503,29.838 12.624,28.717 C13.1@12.624,21.361 16.408,21.361 C15.1@18.161,23.114
NetC14_1: C14.1 C15.2 F1.2 L2.1 RT2.2 RT3.2 | length 72.1
  Top Layer w2.667: L2.1@36.503,29.838 38.303,28.038 38.303,24.486 36.932,23.114 C15.2@33.147,23.114 27.114,17.081 RT2.2@27.114,15.05 27.686,14.478 F1.2@34.163,14.478 37.592,14.478 RT3.2@39.688,16.573
  Bottom Layer w2.667: L2.1@36.503,29.838 38.303,28.038 38.303,24.486 36.932,23.114 C15.2@33.147,23.114 27.114,17.081 RT2.2@27.114,15.05 27.686,14.478 F1.2@34.163,14.478 37.592,14.478 RT3.2@39.688,16.573
NetC19_1: C19.1 R4.2 | length 1.9
  Bottom Layer w0.508: R4.2@8.585,97.536 C19.1@10.465,97.536
NetC19_2: C19.2 C21.1 R3.2 R7.1 U2.5 | length 8.6
  Bottom Layer w0.254: C21.1@10.287,93.828 10.317,93.797 U2.5@12.331,93.797 12.471,93.797 12.471,94.386
  Bottom Layer w0.635: C19.2@10.592,95.758 12.395,95.758 R7.1@12.471,95.834 ; 12.471,94.386 12.471,95.021
  Bottom Layer w0.889: 12.471,95.021 R7.1@12.471,95.834 12.471,96.444 12.852,96.825 R3.2@12.852,98.171
NetC20_2: C20.2 R6.1 U2.7 | length 4.5
  Bottom Layer w0.254: U2.7@16.675,93.297 17.783,93.297 18.212,93.726
  Bottom Layer w0.381: 18.212,93.726 C20.2@18.72,94.234
  Bottom Layer w0.508: R6.1@20.726,94.234 R6.1@20.803,94.158
  Bottom Layer w0.762: C20.2@18.72,94.234 R6.1@20.726,94.234
NetC21_2: C21.2 D3.2 R4.1 U2.4 | length 27.8
  Bottom Layer w0.254: 8.687,92.913 8.916,92.684 10.54,92.684 11.153,93.297 U2.4@12.331,93.297
  Bottom Layer w0.508: 8.687,92.913 8.509,93.091 C21.2@8.509,93.828 ; R4.1@8.712,95.758 8.509,95.555 C21.2@8.509,93.828 ; D3.2@15.037,87.351 13.792,86.106 5.207,86.106 4.597,86.716 4.597,91.472 6.953,93.828 C21.2@8.509,93.828
NetC22_2: C22.2 R13.2 U2.9 | length 4.3
  Bottom Layer w0.254: U2.9@16.675,92.296 17.711,92.296 18.11,91.897
  Bottom Layer w0.508: 18.11,91.897 C22.2@18.72,91.288 18.72,89.548 R13.2@18.682,89.51
NetC23_1: C23.1 U2.2 | length 4.6
  Bottom Layer w0.254: 10.618,91.035 11.162,91.579 11.162,91.931 11.526,92.296 U2.2@12.331,92.296
  Bottom Layer w0.508: C23.1@8.636,90.526 9.627,90.526 10.136,91.035 10.618,91.035
NetC24_2: C24.2 R12.2 U2.1 | length 4.1
  Bottom Layer w0.254: 12.37,91.11 U2.1@12.37,91.757
  Bottom Layer w0.508: C24.2@10.795,89.967 12.471,89.967 R12.2@12.649,89.789 12.649,90.932 12.37,91.211
NetC25_1: C25.1 R16.1 R17.1 R18.2 U3.5 | length 7.1
  Bottom Layer w0.356: R16.1@11.049,84.747 11.9,84.747 12.169,84.478 U3.5@13.117,84.478
  Bottom Layer w0.508: R18.2@6.096,84.747 R17.1@7.747,84.747 C25.1@9.398,84.747 R16.1@11.049,84.747
NetC26_1: C26.1 R19.1 | length 2.4
  Bottom Layer w1.143: C26.1@25.961,81.915 28.192,81.915 R19.1@28.319,82.042
NetC27_2: C27.2 D6.1 Q5.3 | length 14.2
  Bottom Layer w0.508: C27.2@2.286,77.089 2.464,77.267 Q5.3@2.464,80.101
  Bottom Layer w0.889: C27.2@2.286,77.089 2.286,76.073 1.651,75.438 1.651,68.485 D6.1@3.207,66.929
NetC28_1: C28.1 R22.1 | length 4.4
  Bottom Layer w1.27: R22.1@82.575,74.653 83.704,74.653 85.52,72.837 C28.1@85.52,72.136
NetC29_1: C29.1 R24.1 R25.1 R26.1 U4.5 | length 8.3
  Bottom Layer w0.356: R24.1@63.246,70.612 63.35,70.508 U4.5@65.314,70.508
  Bottom Layer w0.508: R26.1@61.379,66.294 61.29,66.383 C29.1@61.29,68.453 61.379,68.542 R25.1@61.379,70.485 61.506,70.612 R24.1@63.246,70.612
NetC30_2: C30.2 R27.1 U5.5 | length 3.9
  Bottom Layer w0.508: R27.1@65.405,61.43 C30.2@65.405,59.563 65.405,57.785 65.445,57.745 U5.5@65.646,57.745
NetC31_2: C31.2 D10.3 D13.2 U1.4 U5.1 | length 94.6
  Top Layer w0.508: v1@54.458,60.147 54.458,58.623 52.324,56.49 52.324,52.197 54.483,50.038 v1(59.284,50.038) 61.493,50.038 63.678,47.854 U1.4@63.678,45.822 ; v1@54.481,60.221 52.883,61.819 52.883,68.351 54.991,70.46 66.091,70.46 70.053,74.422 74.473,74.422 77.699,77.648 80.569,77.648 82.423,79.502 82.423,89.992 v1(82.474,90.043)
  Bottom Layer w0.508: v1(54.458,60.198) 55.118,60.198 57.089,62.169 D10.3@60.706,62.169 ; v1(59.284,50.038) 60.833,51.587 C31.2@60.833,51.816 ; C31.2@60.706,51.943 60.846,52.083 U5.1@60.846,53.935 ; v1(82.474,90.043) 84.074,90.043 85.344,91.313 D13.2@87.503,91.313
NetC33_1: C33.1 R35.1 R37.2 U6.2 | length 9.5
  Bottom Layer w0.508: R35.1@66.091,33.312 65.342,33.312 64.501,32.471 U6.2@64.501,30.109 64.501,29.606 65.837,28.27 66.434,28.27 R37.2@66.599,28.105 66.599,26.314 C33.1@66.726,26.187
NetC33_2: C33.2 R40.2 | length 1.7
  Bottom Layer w0.508: R40.2@65.075,24.587 C33.2@66.726,24.587
NetC34_1: C34.1 R42.1 U1.1 | length 15.2
  Bottom Layer w0.508: C34.1@60.084,24.447 R42.1@60.084,26.149 60.084,34.608 U1.1@63.678,38.202
NetC34_2: C34.2 R44.2 | length 1.7
  Bottom Layer w0.508: C34.2@60.122,22.809 R44.2@61.773,22.809
NetC35_1: C35.1 R36.2
NetD3_1: D3.1 R13.1 R15.2 | length 4.1
  Bottom Layer w0.508: D3.1@18.288,87.3 D3.1@18.339,87.351 R15.2@20.206,87.351 R13.1@20.206,89.51
NetD4_1: D4.1 Q5.1 R18.1 R20.2 R21.1 | length 12.7
  Bottom Layer w0.508: R20.2@1.397,83.896 1.397,85.611 D4.1@2.337,86.55 4.445,84.442 4.445,83.693 4.991,83.147 R18.1@6.096,83.147 6.096,82.423 5.08,81.407 R21.1@5.08,81.28 ; Q5.1@1.514,82.001 R20.2@1.514,83.779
